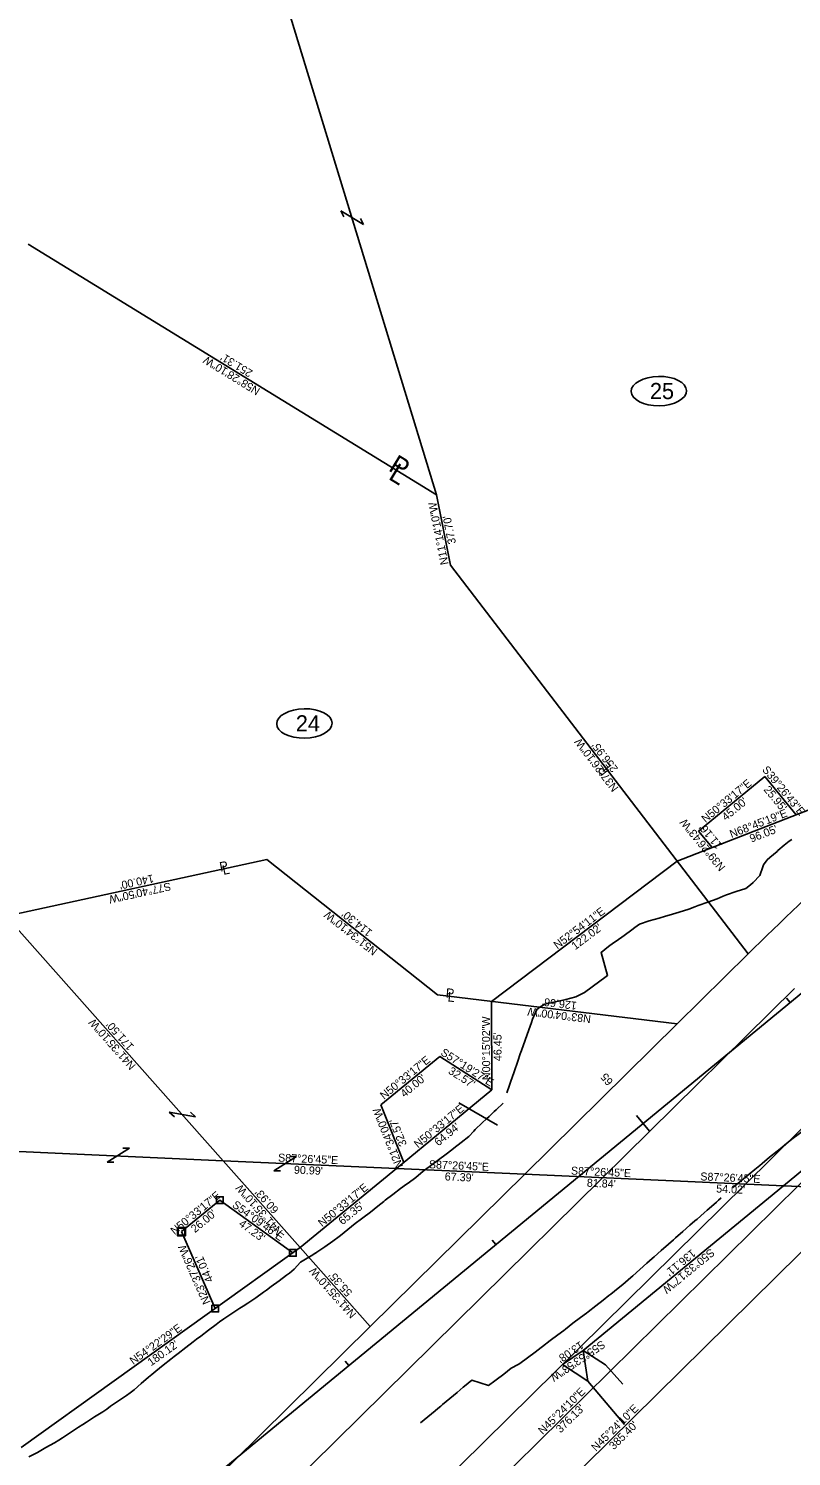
# Model space of a CAD drawing. Extents: x 1145508 to 2262867, y -3126236 to 2021677.
# Drawn here: x 1149147 to 1149547, y 2018793 to 2019543 of the extents above; entities that cross this region are included whole.
import ezdxf

# ---------------------------------------------------------------- set-up
doc = ezdxf.new("R2010")
doc.units = 0
for name, color, linetype in [('Default', 7, 'Continuous'), ('DSN_RDWY_Alignment Annotation', 7, 'Continuous'), ('DSN_RDWY_Const Limits', 7, 'Continuous'), ('DSN_ROW_Annotation', 7, 'Continuous'), ('DSN_ROW_Esmnt', 7, 'Continuous'), ('DSN_ROW_Line', 7, 'Continuous'), ('DSN_ROW_Line-Annotation', 7, 'Continuous'), ('DSN_ROW_Prop-Line', 7, 'Continuous'), ('DSN_ROW_Prop-Line-Annotation', 7, 'Continuous'), ('E_Const Align', 7, 'Continuous'), ('E_Proposed ROW and Easements', 7, 'Continuous'), ('EX_QSECTION', 7, 'Continuous'), ('EX_ROW', 7, 'Continuous'), ('EX_ROW_ANNOT', 7, 'Continuous'), ('EX_SIGN', 7, 'Continuous')]:
    doc.layers.add(name, color=color, linetype=linetype)

msp = doc.modelspace()

# ---------------------------------------------------------------- linework, layer by layer
at = {"layer": 'Default'}
msp.add_line((1149548.89, 2019038.9), (1148996.69, 2018494.41), dxfattribs=at)
at = {"layer": 'DSN_RDWY_Alignment Annotation'}
for p, q in [((1149544.79, 2019033.95), (1149546.7, 2019031.63)), ((1149466.08, 2018972.22), (1149472.83, 2018964.02)), ((1149390.35, 2018906.88), (1149392.25, 2018904.56)), ((1149313.12, 2018843.35), (1149315.03, 2018841.03))]:
    msp.add_line(p, q, dxfattribs=at)
at = {"layer": 'DSN_RDWY_Const Limits'}
for points in [[(1149397.92, 2018984.23), (1149399.34, 2018988.19), (1149399.89, 2018989.72), (1149401.82, 2018995.24), (1149403.69, 2019000.83), (1149405.07, 2019004.74), (1149405.64, 2019006.33), (1149407.62, 2019011.79), (1149409.6, 2019017.26), (1149410.94, 2019021.18), (1149411.5, 2019022.83), (1149413.73, 2019027.99), (1149415.35, 2019029.16), (1149417.98, 2019030.68), (1149421.81, 2019031.55), (1149423.44, 2019031.92), (1149428.9, 2019033.15), (1149434.18, 2019034.61), (1149437.41, 2019036.1), (1149438.74, 2019036.94), (1149442.78, 2019039.89), (1149446.83, 2019042.84), (1149449.47, 2019044.78), (1149450.87, 2019045.8), (1149447.4, 2019057.88), (1149451.37, 2019060.93), (1149453.97, 2019062.84), (1149455.43, 2019063.87), (1149459.47, 2019066.82), (1149463.51, 2019069.79), (1149465.13, 2019070.97), (1149466.31, 2019071.83), (1149467.56, 2019072.74), (1149472.68, 2019074.38), (1149477.93, 2019075.87), (1149481.3, 2019076.86), (1149483.14, 2019077.4), (1149488.33, 2019078.96), (1149493.41, 2019080.66), (1149496.61, 2019081.78), (1149498.43, 2019082.43), (1149503.45, 2019084.19), (1149508.38, 2019086.07), (1149511.43, 2019087.38), (1149513.17, 2019088.12), (1149518.23, 2019089.84), (1149523.38, 2019091.45), (1149525.83, 2019093.42), (1149527.27, 2019094.59), (1149530.73, 2019098.25), (1149532.23, 2019102.72), (1149532.61, 2019103.84), (1149534.6, 2019106.47), (1149535.96, 2019107.64), (1149539.74, 2019110.92), (1149540.23, 2019111.35), (1149543.52, 2019114.19), (1149546.1, 2019116.24), (1149547.6, 2019117.1)], [(1149528.11, 2018944.05), (1149530.65, 2018946.11), (1149531.99, 2018947.2), (1149535.86, 2018950.37), (1149539.74, 2018953.53), (1149542.23, 2018955.56), (1149543.61, 2018956.68), (1149547.49, 2018959.84), (1149551.48, 2018962.86), (1149553.13, 2018964), (1149554.34, 2018964.84), (1149555.6, 2018965.72), (1149559.72, 2018968.59), (1149563.81, 2018971.49), (1149566.45, 2018973.36), (1149567.89, 2018974.39), (1149571.98, 2018977.29), (1149575.92, 2018980.37), (1149578.55, 2018982.18), (1149580.12, 2018983.14), (1149584.19, 2018986.06), (1149588.03, 2018989.26), (1149590.65, 2018991.09)], [(1149147.27, 2018793.1), (1149149.7, 2018794.43), (1149151.73, 2018795.54), (1149156.19, 2018797.99), (1149160.64, 2018800.45), (1149162.88, 2018801.91), (1149164.84, 2018803.23), (1149169.07, 2018805.95), (1149173.3, 2018808.68), (1149175.47, 2018810.08), (1149177.53, 2018811.41), (1149181.74, 2018814.15), (1149185.99, 2018816.86), (1149188.05, 2018818.27), (1149190.14, 2018819.69), (1149194.27, 2018822.53), (1149198.41, 2018825.38), (1149200.4, 2018826.76), (1149202.4, 2018828.4), (1149206.19, 2018831.66), (1149209.98, 2018834.92), (1149211.73, 2018836.44), (1149213.76, 2018838.2), (1149217.68, 2018841.31), (1149221.63, 2018844.38), (1149223.41, 2018845.76), (1149225.57, 2018847.45), (1149229.51, 2018850.53), (1149233.48, 2018853.58), (1149235.23, 2018854.9), (1149237.47, 2018856.59), (1149241.46, 2018859.62), (1149245.45, 2018862.65), (1149247.18, 2018863.97), (1149249.46, 2018865.63), (1149253.68, 2018868.37), (1149257.9, 2018871.12), (1149259.69, 2018872.28), (1149262.11, 2018873.86), (1149266.34, 2018876.6), (1149270.4, 2018879.53), (1149271.91, 2018880.64), (1149274.43, 2018882.5), (1149278.46, 2018885.48), (1149282.45, 2018888.49), (1149283.88, 2018889.65), (1149286.33, 2018891.64), (1149289.77, 2018895.34), (1149294.13, 2018897.91), (1149295.65, 2018898.85), (1149297.39, 2018900), (1149297.56, 2018900.12), (1149298.35, 2018900.65), (1149302.52, 2018903.45), (1149306.65, 2018906.29), (1149310.06, 2018908.72), (1149310.68, 2018909.27), (1149314.49, 2018912.51), (1149318.4, 2018915.63), (1149321.66, 2018918.06), (1149322.41, 2018918.62), (1149326.4, 2018921.65), (1149330.3, 2018924.77), (1149333.45, 2018927.23), (1149334.24, 2018927.85), (1149338.2, 2018930.91), (1149342.2, 2018933.91), (1149345.39, 2018936.26), (1149346.24, 2018936.88), (1149350.27, 2018939.84), (1149354.1, 2018943.06), (1149357.26, 2018945.35), (1149358.17, 2018945.99), (1149362.18, 2018948.98), (1149366.15, 2018952.02), (1149369.15, 2018954.36), (1149370.1, 2018955.1), (1149374.05, 2018958.17), (1149377.99, 2018961.25), (1149380.59, 2018964.03), (1149381.43, 2018964.94), (1149385.05, 2018968.41), (1149387.37, 2018970.52), (1149388.7, 2018971.84), (1149391.36, 2018974.45), (1149392.31, 2018975.32), (1149395.98, 2018978.72)], [(1149516.59, 2018934.44), (1149519.19, 2018936.7), (1149528.11, 2018944.05)], [(1149352.63, 2018811.07), (1149356.53, 2018814.2), (1149360.41, 2018817.35), (1149361.76, 2018818.49), (1149363.34, 2018819.83), (1149363.5, 2018819.96), (1149364.23, 2018820.57), (1149368.06, 2018823.79), (1149371.89, 2018827.01), (1149375.08, 2018829.69), (1149375.72, 2018830.22), (1149379.55, 2018833.43), (1149388.34, 2018830.62), (1149391.64, 2018833), (1149392.39, 2018833.57), (1149396.35, 2018836.62), (1149400.33, 2018839.65), (1149403.86, 2018841.66), (1149404.75, 2018842.16), (1149408.82, 2018845.08), (1149412.8, 2018848.1), (1149415.94, 2018850.51), (1149416.78, 2018851.14), (1149420.78, 2018854.15), (1149424.79, 2018857.14), (1149427.89, 2018859.49), (1149428.77, 2018860.18), (1149432.7, 2018863.27), (1149436.68, 2018866.3), (1149439.73, 2018868.58), (1149440.69, 2018869.29), (1149444.66, 2018872.34), (1149448.58, 2018875.44), (1149451.55, 2018877.79), (1149452.5, 2018878.55), (1149456.43, 2018881.64), (1149458.87, 2018883.62), (1149460.27, 2018884.85), (1149463.05, 2018887.31), (1149464.02, 2018888.16), (1149467.77, 2018891.47), (1149471.5, 2018894.81), (1149474.2, 2018897.2), (1149475.25, 2018898.12), (1149478.99, 2018901.44), (1149482.72, 2018904.77), (1149485.38, 2018907.13), (1149486.47, 2018908.09), (1149490.24, 2018911.37), (1149494, 2018914.68), (1149496.64, 2018917), (1149497.76, 2018917.98), (1149501.52, 2018921.28), (1149503.02, 2018922.6), (1149505.29, 2018924.56), (1149507.93, 2018926.87), (1149509.06, 2018927.85), (1149510.5, 2018929.11)]]:
    msp.add_lwpolyline(points, dxfattribs=at)
at = {"layer": 'DSN_ROW_Esmnt'}
for p, q in [((1149498.61, 2019121.56), (1149533.36, 2019150.15)), ((1149533.36, 2019150.15), (1149549.85, 2019130.11)), ((1149505.7, 2019112.95), (1149498.61, 2019121.56)), ((1149331.89, 2018977.93), (1149362.78, 2019003.34)), ((1149362.78, 2019003.34), (1149390.2, 2018985.75)), ((1149343.87, 2018947.63), (1149331.89, 2018977.93)), ((1149227.38, 2018911.36), (1149247.46, 2018927.88)), ((1149247.46, 2018927.88), (1149285.75, 2018900.23)), ((1149245.02, 2018871.04), (1149227.38, 2018911.36)), ((1149440.42, 2018832.88), (1149438, 2018848.96)), ((1149449.74, 2018841.47), (1149438, 2018848.96)), ((1149427.16, 2018841.63), (1149440.42, 2018832.88)), ((1149449.74, 2018841.47), (1149458.84, 2018831.33)), ((1149440.42, 2018832.88), (1149459.65, 2018810.12))]:
    msp.add_line(p, q, dxfattribs=at)
for points in [[(1149245.62, 2018929.69), (1149249.22, 2018929.69), (1149249.22, 2018926.09), (1149245.62, 2018926.09)], [(1149225.17, 2018913.54), (1149229.49, 2018913.54), (1149229.49, 2018909.22), (1149225.17, 2018909.22)], [(1149225.54, 2018913.18), (1149229.14, 2018913.18), (1149229.14, 2018909.58), (1149225.54, 2018909.58)], [(1149283.91, 2018902.04), (1149287.51, 2018902.04), (1149287.51, 2018898.44), (1149283.91, 2018898.44)], [(1149243.18, 2018872.85), (1149246.78, 2018872.85), (1149246.78, 2018869.25), (1149243.18, 2018869.25)]]:
    msp.add_lwpolyline(points, close=True, dxfattribs=at)
at = {"layer": 'DSN_ROW_Line'}
for p, q in [((1149487.33, 2019105.8), (1149576.85, 2019140.61)), ((1149390, 2019032.2), (1149487.33, 2019105.8)), ((1149390.2, 2018985.75), (1149390, 2019032.2)), ((1149340.06, 2018944.5), (1149390.2, 2018985.75)), ((1149543.1, 2018935.44), (1149592.44, 2018976.03)), ((1149289.59, 2018902.98), (1149340.06, 2018944.5)), ((1149543.1, 2018935.44), (1149438, 2018848.96)), ((1149143.19, 2018798.06), (1149289.59, 2018902.98)), ((1149438, 2018848.96), (1149427.16, 2018841.63))]:
    msp.add_line(p, q, dxfattribs=at)
at = {"layer": 'DSN_ROW_Line-Annotation'}
for centre in [(1149477.75, 2019352.47), (1149291.8, 2019178.05)]:
    msp.add_ellipse(centre, major_axis=(14.54, 0.23), ratio=0.529773, dxfattribs=at)
at = {"layer": 'DSN_ROW_Prop-Line'}
for p, q in [((1149195.46, 2019840.44), (1149361.07, 2019298.1)), ((1149361.07, 2019298.1), (1149146.87, 2019429.52)), ((1149368.42, 2019261.12), (1149361.07, 2019298.1)), ((1149524.62, 2019057.09), (1149368.42, 2019261.12)), ((1149272.1, 2019106.7), (1149135.32, 2019076.83)), ((1149361.63, 2019035.65), (1149272.1, 2019106.7)), ((1149249.15, 2018948.55), (1149135.32, 2019076.83)), ((1149487.37, 2019020.36), (1149361.63, 2019035.65)), ((1149289.59, 2018902.98), (1149249.15, 2018948.55)), ((1149295.7, 2018683.91), (1149563.53, 2018948)), ((1149320.31, 2018671.82), (1149594.73, 2018942.42)), ((1149326.33, 2018861.58), (1149289.59, 2018902.98))]:
    msp.add_line(p, q, dxfattribs=at)
at = {"layer": 'DSN_ROW_Prop-Line-Annotation'}
for p, q in [((1149312.48, 2019443.9), (1149310.87, 2019447.06)), ((1149310.87, 2019447.06), (1149322.83, 2019439.84)), ((1149322.83, 2019439.84), (1149321.22, 2019443.01)), ((1149223.55, 2018971.63), (1149220.9, 2018973.99)), ((1149220.9, 2018973.99), (1149234.66, 2018971.62)), ((1149234.66, 2018971.62), (1149232.02, 2018973.98)), ((1149188.23, 2018947.8), (1149200.08, 2018955.19)), ((1149200.08, 2018955.19), (1149196.53, 2018955.19)), ((1149275.76, 2018943.34), (1149287.61, 2018950.72)), ((1149287.61, 2018950.72), (1149284.07, 2018950.72)), ((1149191.77, 2018947.8), (1149188.23, 2018947.8)), ((1149279.31, 2018943.34), (1149275.76, 2018943.34))]:
    msp.add_line(p, q, dxfattribs=at)
at = {"layer": 'E_Const Align'}
msp.add_line((1148677.53, 2018316.54), (1149639.88, 2019108.3), dxfattribs=at)
at = {"layer": 'E_Proposed ROW and Easements'}
msp.add_lwpolyline([(1149245.02, 2018871.04), (1149227.38, 2018911.36)], dxfattribs=at)
at = {"layer": 'EX_QSECTION'}
for p, q in [((1149008.48, 2018959.29), (1149249.15, 2018948.55)), ((1149249.15, 2018948.55), (1149340.06, 2018944.5)), ((1149340.06, 2018944.5), (1149407.38, 2018941.49)), ((1149407.38, 2018941.49), (1149489.14, 2018937.85)), ((1149489.14, 2018937.85), (1149543.1, 2018935.44)), ((1149543.1, 2018935.44), (1150337.23, 2018900.01))]:
    msp.add_line(p, q, dxfattribs=at)
at = {"layer": 'EX_ROW'}
for p, q in [((1149487.37, 2019020.36), (1149524.62, 2019057.09)), ((1149524.62, 2019057.09), (1149527.83, 2019060.26)), ((1149407.38, 2018941.49), (1149487.37, 2019020.36)), ((1149523.2, 2018936.33), (1149587.51, 2018999.73)), ((1149326.33, 2018861.58), (1149407.38, 2018941.49)), ((1149326.65, 2018742.52), (1149523.2, 2018936.33)), ((1149007.06, 2018546.76), (1149326.33, 2018861.58))]:
    msp.add_line(p, q, dxfattribs=at)
msp.add_arc((1150698.28, 2017873.24), 1667.02, 132.0621, 134.5973, dxfattribs=at)
at = {"layer": 'EX_SIGN'}
msp.add_line((1149372.88, 2018979), (1149393.17, 2018967.3), dxfattribs=at)

# ---------------------------------------------------------------- texts
at = {"layer": 'DSN_RDWY_Alignment Annotation'}
msp.add_text('65', height=4.2, rotation=129.44534, dxfattribs=at).set_placement((1149454.02, 2018990.19))
at = {"layer": 'DSN_ROW_Annotation'}
for s, rotation, p in [('N58°28\'10"W', 148.46953, (1149268.9, 2019353.6)), ("251.31'", 148.46953, (1149265.04, 2019363)), ('N11°14\'10"W', 101.23619, (1149367.38, 2019261.71)), ("37.70'", 101.23619, (1149371.34, 2019272.61)), ('N37°26\'10"W', 127.43619, (1149456.78, 2019144.22)), ("256.95'", 127.43619, (1149456.56, 2019154.38)), ('S39°26\'43"E', 309.44534, (1149531.65, 2019153.65)), ('N50°33\'17"E', 39.44534, (1149502.24, 2019125.71)), ("45.00'", 39.44534, (1149512.93, 2019126.74)), ("25.95'", 309.44534, (1149532.49, 2019143.19)), ('N68°45\'19"E', 21.24477, (1149515.86, 2019117.86)), ('N39°26\'43"W', 129.44534, (1149512.93, 2019102.73)), ("11.16'", 129.44534, (1149511.27, 2019114.2)), ("96.05'", 21.24477, (1149526.34, 2019115.5)), ('S77°40\'50"W', 192.31953, (1149221.26, 2019094.67)), ("140.00'", 192.31953, (1149212.25, 2019098.85)), ('N51°34\'10"W', 141.56953, (1149330.46, 2019059.24)), ("114.30'", 141.56953, (1149327.76, 2019069.04)), ('N52°54\'11"E', 37.09693, (1149424.51, 2019059.43)), ("122.02'", 37.09693, (1149433.87, 2019058.99)), ("126.66'", 173.06677, (1149434.9, 2019031.88)), ('N83°04\'00"W', 173.06677, (1149442.32, 2019024.93)), ('N41°35\'10"W', 131.58619, (1149203.55, 2018998.58)), ("171.50'", 131.58619, (1149202.6, 2019008.7)), ('N00°15\'02"W', 90.25044, (1149389.28, 2018990.91)), ("46.45'", 90.25044, (1149395.24, 2019000.85)), ('N50°33\'17"E', 39.44534, (1149333.59, 2018980.49)), ('S57°19\'27"E', 327.32403, (1149362.87, 2019004.35)), ("32.57'", 327.32403, (1149366.88, 2018994.65)), ("40.00'", 39.44534, (1149344.28, 2018981.51)), ('N21°34\'00"W', 111.56664, (1149343.68, 2018945.65)), ('N50°33\'17"E', 39.44534, (1149351.38, 2018954.98)), ("32.57'", 111.56664, (1149345.62, 2018957.07)), ("64.94'", 39.44534, (1149362.07, 2018956.01)), ('N41°35\'10"W', 131.58619, (1149280.69, 2018911.66)), ('N50°33\'17"E', 39.44534, (1149301.08, 2018913.6)), ('N50°33\'17"E', 39.44534, (1149223.67, 2018909.48)), ("60.93'", 131.58619, (1149278.6, 2018923.05)), ("26.00'", 39.44534, (1149234.36, 2018910.5)), ('S54°09\'46"E', 324.16268, (1149253.54, 2018924.6)), ("65.35'", 39.44534, (1149311.77, 2018914.62)), ("47.23'", 324.16268, (1149257.01, 2018914.69)), ('N23°37\'26"W', 113.62381, (1149242.61, 2018874.29)), ("44.01'", 113.62381, (1149244.14, 2018885.77)), ('S50°33\'17"W', 219.44534, (1149504.84, 2018902.8)), ("136.11'", 219.44534, (1149494.93, 2018902.4)), ('N41°35\'10"W', 131.58619, (1149319.28, 2018868.17)), ("55.35'", 131.58619, (1149317.19, 2018879.57)), ('N54°22\'29"E', 35.62531, (1149202, 2018841.32)), ("180.12'", 35.62531, (1149211.35, 2018840.63)), ('S55°53\'53"W', 214.10199, (1149447.8, 2018854.51)), ("13.08'", 214.10199, (1149436.47, 2018854.09)), ('N45°24\'10"E', 44.5973, (1149416.83, 2018804.62)), ("376.13'", 44.5973, (1149426.17, 2018805.4)), ('N45°24\'10"E', 44.5973, (1149444.74, 2018795.79)), ("385.40'", 44.5973, (1149454.08, 2018796.57))]:
    msp.add_text(s, height=4.2, rotation=rotation, dxfattribs=at).set_placement(p)
at = {"layer": 'DSN_ROW_Line-Annotation'}
for s, p in [('25', (1149473.07, 2019348.26)), ('24', (1149287.29, 2019173.84))]:
    msp.add_text(s, height=8.5, dxfattribs=at).set_placement(p)
at = {"layer": 'DSN_ROW_Prop-Line-Annotation'}
for s, height, rotation, p in [('P', 10, 328.58568, (1149335.38, 2019311.04)), ('L', 10, 328.58568, (1149335.37, 2019306.55)), ('P', 5, 127.77049, (1149452, 2019153.14)), ('L', 5, 127.77049, (1149452.8, 2019155.24)), ('P', 5, 11.22721, (1149247.78, 2019100.21)), ('L', 5, 11.22721, (1149249.3, 2019098.55)), ('P', 5, 355.53411, (1149365.78, 2019034.13)), ('L', 5, 355.53411, (1149366.79, 2019032.13))]:
    msp.add_text(s, height=height, rotation=rotation, dxfattribs=at).set_placement(p)
at = {"layer": 'EX_ROW_ANNOT'}
for s, p in [('S87°26\'45"E', (1149277.9, 2018948.17)), ('S87°26\'45"E', (1149277.9, 2018948.17)), ("90.99'", (1149286.23, 2018941.79)), ("90.99'", (1149286.23, 2018941.79)), ('S87°26\'45"E', (1149357.01, 2018944.64)), ('S87°26\'45"E', (1149357.01, 2018944.64)), ('S87°26\'45"E', (1149431.55, 2018941.32)), ('S87°26\'45"E', (1149431.55, 2018941.32)), ("67.39'", (1149365.35, 2018938.26)), ("67.39'", (1149365.35, 2018938.26)), ("81.84'", (1149439.89, 2018934.94)), ("81.84'", (1149439.89, 2018934.94)), ('S87°26\'45"E', (1149499.42, 2018938.29)), ('S87°26\'45"E', (1149499.42, 2018938.29)), ("54.02'", (1149507.75, 2018931.91)), ("54.02'", (1149507.75, 2018931.91))]:
    msp.add_text(s, height=4.2, rotation=357.44576, dxfattribs=at).set_placement(p)

doc.saveas('drawing.dxf')
